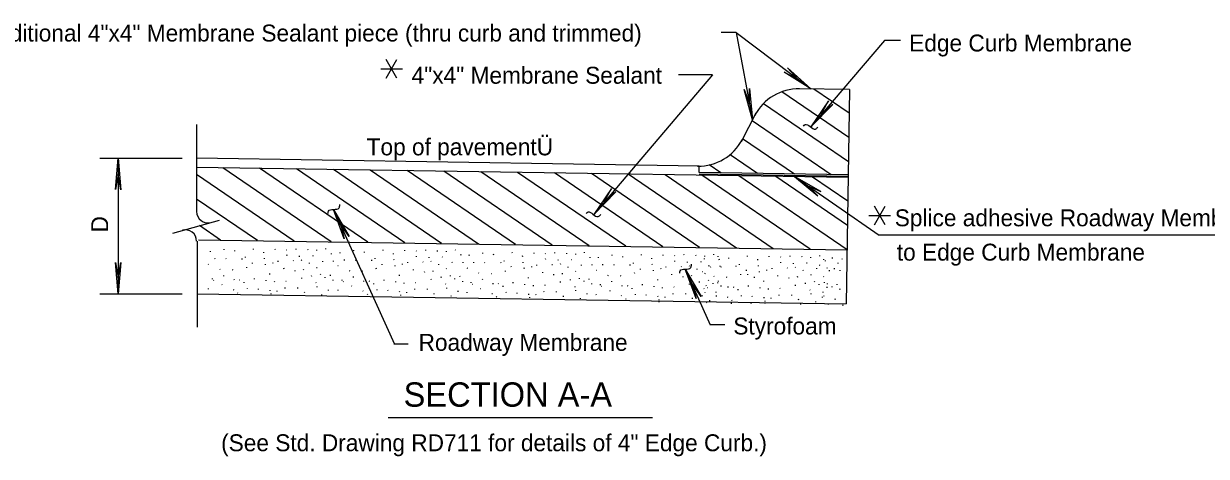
# Model space of a CAD drawing. Extents: x 1000 to 1036, y 1000 to 1022.7.
# Drawn here: x 1012.07 to 1022.98, y 1008.69 to 1012.68 of the extents above; entities that cross this region are included whole.
import ezdxf

# ---------------------------------------------------------------- set-up
doc = ezdxf.new("R2010")
doc.units = 0
for name, color, linetype in [('rd_Detail Annotation_z_n', 7, 'Continuous'), ('rd_Details_z_n', 7, 'Continuous'), ('rd_Dimensions_z_n', 7, 'Continuous'), ('rd_Misc Label_z_n', 7, 'Continuous'), ('rd_Symbols_z_n', 7, 'Continuous')]:
    doc.layers.add(name, color=color, linetype=linetype)

msp = doc.modelspace()

# ---------------------------------------------------------------- linework, layer by layer
at = {"layer": 'rd_Detail Annotation_z_n'}
for p, q in [((1018.644, 1012.601), (1018.506, 1012.601)), ((1018.644, 1012.601), (1018.797, 1011.796)), ((1018.644, 1012.601), (1019.335, 1012.08)), ((1020.013, 1012.528), (1019.334, 1011.729)), ((1020.161, 1012.528), (1020.013, 1012.528)), ((1018.427, 1012.21), (1017.332, 1010.922)), ((1018.427, 1012.21), (1018.112, 1012.21)), ((1019.182, 1011.273), (1019.963, 1010.731)), ((1014.932, 1010.968), (1015.493, 1009.723)), ((1023.768, 1010.731), (1019.963, 1010.731)), ((1018.176, 1010.417), (1018.407, 1009.903)), ((1018.541, 1009.903), (1018.407, 1009.903)), ((1015.621, 1009.723), (1015.487, 1009.723)), ((1015.437, 1009.045), (1017.874, 1009.045))]:
    msp.add_line(p, q, dxfattribs=at)
at = {"layer": 'rd_Details_z_n'}
for p, q in [((1019.691, 1012.074), (1019.226, 1012.081)), ((1019.687, 1011.857), (1019.362, 1012.079)), ((1019.691, 1012.074), (1019.66, 1010.095)), ((1019.684, 1011.633), (1019.067, 1012.054)), ((1018.828, 1011.856), (1018.691, 1011.593)), ((1019.68, 1011.408), (1018.896, 1011.944)), ((1013.669, 1011.752), (1013.669, 1010.947)), ((1019.523, 1011.288), (1018.793, 1011.787)), ((1019.183, 1011.294), (1018.705, 1011.62)), ((1018.305, 1011.366), (1013.669, 1011.44)), ((1018.843, 1011.299), (1018.589, 1011.473)), ((1019.678, 1011.261), (1013.669, 1011.356)), ((1014.909, 1010.669), (1013.91, 1011.352)), ((1015.249, 1010.664), (1014.25, 1011.347)), ((1015.589, 1010.659), (1014.59, 1011.342)), ((1015.929, 1010.653), (1014.93, 1011.336)), ((1016.269, 1010.648), (1015.27, 1011.331)), ((1016.609, 1010.643), (1015.61, 1011.326)), ((1016.949, 1010.637), (1015.95, 1011.32)), ((1017.289, 1010.632), (1016.29, 1011.315)), ((1017.628, 1010.627), (1016.63, 1011.309)), ((1017.968, 1010.621), (1016.97, 1011.304)), ((1018.308, 1010.616), (1017.31, 1011.299)), ((1018.648, 1010.611), (1017.65, 1011.293)), ((1018.304, 1011.308), (1018.305, 1011.366)), ((1019.679, 1011.286), (1018.304, 1011.308)), ((1019.679, 1011.273), (1018.304, 1011.294)), ((1018.503, 1011.304), (1018.396, 1011.378)), ((1014.569, 1010.675), (1013.669, 1011.29)), ((1018.988, 1010.605), (1017.99, 1011.288)), ((1019.328, 1010.6), (1018.33, 1011.283)), ((1019.668, 1010.595), (1018.67, 1011.277)), ((1019.671, 1010.82), (1019.01, 1011.272)), ((1019.675, 1011.044), (1019.35, 1011.266)), ((1014.229, 1010.68), (1013.669, 1011.063)), ((1013.45, 1010.749), (1013.879, 1010.869)), ((1013.889, 1010.685), (1013.695, 1010.818)), ((1013.673, 1010.675), (1013.673, 1009.879)), ((1013.685, 1010.688), (1019.668, 1010.595)), ((1013.798, 1010.575), (1013.798, 1010.582)), ((1013.923, 1010.596), (1013.923, 1010.602)), ((1014.022, 1010.581), (1014.022, 1010.588)), ((1014.121, 1010.523), (1014.121, 1010.529)), ((1014.194, 1010.598), (1014.193, 1010.605)), ((1014.29, 1010.566), (1014.289, 1010.573)), ((1014.395, 1010.596), (1014.394, 1010.602)), ((1014.498, 1010.596), (1014.502, 1010.594)), ((1014.503, 1010.54), (1014.502, 1010.547)), ((1014.587, 1010.598), (1014.586, 1010.605)), ((1014.619, 1010.531), (1014.618, 1010.538)), ((1014.697, 1010.592), (1014.696, 1010.599)), ((1014.738, 1010.541), (1014.743, 1010.539)), ((1014.779, 1010.587), (1014.778, 1010.593)), ((1014.861, 1010.601), (1014.86, 1010.608)), ((1014.913, 1010.555), (1014.912, 1010.561)), ((1014.993, 1010.563), (1014.993, 1010.57)), ((1015.119, 1010.584), (1015.118, 1010.591)), ((1015.218, 1010.569), (1015.217, 1010.576)), ((1015.389, 1010.587), (1015.389, 1010.593)), ((1015.485, 1010.555), (1015.485, 1010.561)), ((1015.59, 1010.584), (1015.589, 1010.591)), ((1015.693, 1010.585), (1015.697, 1010.582)), ((1015.698, 1010.529), (1015.697, 1010.535)), ((1015.782, 1010.587), (1015.782, 1010.593)), ((1015.892, 1010.58), (1015.891, 1010.587)), ((1015.933, 1010.529), (1015.938, 1010.527)), ((1015.974, 1010.575), (1015.974, 1010.582)), ((1016.056, 1010.59), (1016.055, 1010.596)), ((1016.108, 1010.543), (1016.107, 1010.55)), ((1016.185, 1010.54), (1016.184, 1010.547)), ((1016.31, 1010.561), (1016.309, 1010.567)), ((1016.409, 1010.546), (1016.408, 1010.553)), ((1016.581, 1010.563), (1016.58, 1010.57)), ((1016.677, 1010.531), (1016.676, 1010.538)), ((1016.781, 1010.561), (1016.781, 1010.567)), ((1016.884, 1010.561), (1016.888, 1010.559)), ((1016.973, 1010.563), (1016.973, 1010.57)), ((1017.084, 1010.557), (1017.083, 1010.564)), ((1017.166, 1010.552), (1017.165, 1010.559)), ((1017.247, 1010.566), (1017.246, 1010.573)), ((1017.501, 1010.541), (1017.501, 1010.548)), ((1017.6, 1010.527), (1017.6, 1010.533)), ((1017.772, 1010.544), (1017.771, 1010.551)), ((1017.973, 1010.541), (1017.972, 1010.548)), ((1018.076, 1010.542), (1018.08, 1010.54)), ((1018.165, 1010.544), (1018.164, 1010.551)), ((1018.275, 1010.538), (1018.274, 1010.544)), ((1018.357, 1010.532), (1018.356, 1010.539)), ((1018.438, 1010.547), (1018.438, 1010.554)), ((1018.479, 1010.53), (1018.479, 1010.536)), ((1018.75, 1010.532), (1018.749, 1010.539)), ((1018.951, 1010.53), (1018.95, 1010.536)), ((1019.053, 1010.53), (1019.058, 1010.528)), ((1019.143, 1010.532), (1019.142, 1010.539)), ((1019.253, 1010.526), (1019.252, 1010.533)), ((1019.416, 1010.535), (1019.416, 1010.542)), ((1013.776, 1010.462), (1013.78, 1010.46)), ((1013.839, 1010.508), (1013.838, 1010.515)), ((1013.937, 1010.513), (1013.941, 1010.511)), ((1014.09, 1010.506), (1014.089, 1010.513)), ((1014.132, 1010.429), (1014.131, 1010.436)), ((1014.185, 1010.468), (1014.185, 1010.475)), ((1014.295, 1010.51), (1014.294, 1010.517)), ((1014.305, 1010.455), (1014.304, 1010.462)), ((1014.374, 1010.469), (1014.373, 1010.476)), ((1014.421, 1010.485), (1014.42, 1010.492)), ((1014.475, 1010.417), (1014.474, 1010.424)), ((1014.559, 1010.495), (1014.564, 1010.492)), ((1014.634, 1010.502), (1014.638, 1010.497)), ((1014.709, 1010.467), (1014.709, 1010.474)), ((1014.776, 1010.432), (1014.78, 1010.43)), ((1014.833, 1010.484), (1014.832, 1010.491)), ((1014.931, 1010.487), (1014.931, 1010.493)), ((1014.971, 1010.451), (1014.975, 1010.449)), ((1015.034, 1010.497), (1015.034, 1010.504)), ((1015.132, 1010.502), (1015.136, 1010.499)), ((1015.285, 1010.494), (1015.285, 1010.501)), ((1015.316, 1010.511), (1015.316, 1010.518)), ((1015.327, 1010.417), (1015.326, 1010.424)), ((1015.381, 1010.456), (1015.38, 1010.463)), ((1015.49, 1010.499), (1015.489, 1010.505)), ((1015.5, 1010.443), (1015.5, 1010.45)), ((1015.569, 1010.458), (1015.568, 1010.464)), ((1015.616, 1010.474), (1015.616, 1010.48)), ((1015.754, 1010.483), (1015.759, 1010.481)), ((1015.814, 1010.52), (1015.814, 1010.526)), ((1015.83, 1010.491), (1015.833, 1010.486)), ((1015.904, 1010.456), (1015.904, 1010.462)), ((1015.971, 1010.421), (1015.975, 1010.418)), ((1016.028, 1010.473), (1016.027, 1010.48)), ((1016.126, 1010.475), (1016.126, 1010.482)), ((1016.162, 1010.428), (1016.167, 1010.425)), ((1016.226, 1010.474), (1016.225, 1010.48)), ((1016.323, 1010.478), (1016.328, 1010.476)), ((1016.477, 1010.471), (1016.476, 1010.478)), ((1016.508, 1010.488), (1016.507, 1010.494)), ((1016.572, 1010.433), (1016.571, 1010.44)), ((1016.681, 1010.475), (1016.68, 1010.482)), ((1016.692, 1010.42), (1016.691, 1010.427)), ((1016.76, 1010.434), (1016.76, 1010.441)), ((1016.808, 1010.45), (1016.807, 1010.457)), ((1016.889, 1010.505), (1016.888, 1010.512)), ((1016.946, 1010.46), (1016.95, 1010.458)), ((1017.006, 1010.497), (1017.005, 1010.503)), ((1017.021, 1010.467), (1017.025, 1010.462)), ((1017.096, 1010.432), (1017.095, 1010.439)), ((1017.125, 1010.506), (1017.129, 1010.504)), ((1017.22, 1010.45), (1017.219, 1010.456)), ((1017.299, 1010.52), (1017.299, 1010.526)), ((1017.318, 1010.452), (1017.317, 1010.458)), ((1017.376, 1010.521), (1017.375, 1010.527)), ((1017.417, 1010.454), (1017.416, 1010.461)), ((1017.514, 1010.459), (1017.519, 1010.457)), ((1017.668, 1010.451), (1017.667, 1010.458)), ((1017.699, 1010.468), (1017.699, 1010.475)), ((1017.763, 1010.413), (1017.763, 1010.42)), ((1017.868, 1010.512), (1017.867, 1010.519)), ((1017.873, 1010.456), (1017.872, 1010.463)), ((1017.952, 1010.415), (1017.951, 1010.422)), ((1017.999, 1010.431), (1017.998, 1010.438)), ((1018.08, 1010.486), (1018.08, 1010.493)), ((1018.137, 1010.441), (1018.142, 1010.438)), ((1018.197, 1010.477), (1018.196, 1010.484)), ((1018.212, 1010.448), (1018.216, 1010.443)), ((1018.287, 1010.413), (1018.286, 1010.42)), ((1018.316, 1010.487), (1018.321, 1010.484)), ((1018.354, 1010.509), (1018.353, 1010.516)), ((1018.395, 1010.442), (1018.394, 1010.449)), ((1018.411, 1010.43), (1018.41, 1010.437)), ((1018.491, 1010.5), (1018.49, 1010.507)), ((1018.492, 1010.447), (1018.497, 1010.445)), ((1018.509, 1010.432), (1018.508, 1010.439)), ((1018.578, 1010.515), (1018.577, 1010.522)), ((1018.646, 1010.44), (1018.645, 1010.447)), ((1018.677, 1010.457), (1018.676, 1010.463)), ((1018.846, 1010.5), (1018.845, 1010.507)), ((1018.85, 1010.444), (1018.85, 1010.451)), ((1018.977, 1010.419), (1018.976, 1010.426)), ((1019.058, 1010.474), (1019.058, 1010.481)), ((1019.115, 1010.429), (1019.12, 1010.426)), ((1019.175, 1010.465), (1019.174, 1010.472)), ((1019.19, 1010.436), (1019.194, 1010.431)), ((1019.294, 1010.475), (1019.299, 1010.473)), ((1019.335, 1010.521), (1019.334, 1010.527)), ((1019.389, 1010.418), (1019.388, 1010.425)), ((1019.412, 1010.456), (1019.417, 1010.453)), ((1019.453, 1010.501), (1019.453, 1010.508)), ((1019.469, 1010.489), (1019.468, 1010.495)), ((1019.487, 1010.421), (1019.486, 1010.427)), ((1019.535, 1010.516), (1019.534, 1010.523)), ((1019.553, 1010.417), (1019.552, 1010.424)), ((1019.587, 1010.469), (1019.586, 1010.476)), ((1019.625, 1010.504), (1019.624, 1010.511)), ((1013.815, 1010.324), (1013.815, 1010.33)), ((1013.824, 1010.314), (1013.827, 1010.312)), ((1013.882, 1010.416), (1013.886, 1010.414)), ((1013.921, 1010.352), (1013.921, 1010.359)), ((1013.998, 1010.412), (1014.003, 1010.409)), ((1014.017, 1010.314), (1014.016, 1010.321)), ((1014.063, 1010.318), (1014.067, 1010.316)), ((1014.204, 1010.323), (1014.203, 1010.33)), ((1014.311, 1010.307), (1014.31, 1010.314)), ((1014.345, 1010.368), (1014.344, 1010.375)), ((1014.577, 1010.397), (1014.577, 1010.403)), ((1014.638, 1010.329), (1014.638, 1010.336)), ((1014.657, 1010.406), (1014.656, 1010.413)), ((1014.731, 1010.348), (1014.73, 1010.355)), ((1014.814, 1010.363), (1014.813, 1010.369)), ((1014.856, 1010.336), (1014.856, 1010.343)), ((1014.904, 1010.356), (1014.903, 1010.363)), ((1014.929, 1010.311), (1014.928, 1010.318)), ((1015.011, 1010.312), (1015.01, 1010.319)), ((1015.077, 1010.404), (1015.082, 1010.402)), ((1015.117, 1010.34), (1015.116, 1010.347)), ((1015.194, 1010.4), (1015.198, 1010.398)), ((1015.399, 1010.312), (1015.398, 1010.319)), ((1015.54, 1010.356), (1015.539, 1010.363)), ((1015.67, 1010.406), (1015.67, 1010.413)), ((1015.773, 1010.385), (1015.772, 1010.392)), ((1015.834, 1010.317), (1015.833, 1010.324)), ((1015.852, 1010.395), (1015.851, 1010.401)), ((1015.926, 1010.337), (1015.925, 1010.344)), ((1016.009, 1010.351), (1016.009, 1010.358)), ((1016.052, 1010.324), (1016.051, 1010.331)), ((1016.099, 1010.344), (1016.098, 1010.351)), ((1016.268, 1010.381), (1016.273, 1010.379)), ((1016.308, 1010.317), (1016.307, 1010.324)), ((1016.385, 1010.377), (1016.389, 1010.375)), ((1016.518, 1010.394), (1016.517, 1010.401)), ((1016.731, 1010.333), (1016.73, 1010.34)), ((1016.862, 1010.383), (1016.861, 1010.389)), ((1016.964, 1010.362), (1016.963, 1010.369)), ((1017.043, 1010.371), (1017.043, 1010.378)), ((1017.117, 1010.313), (1017.116, 1010.321)), ((1017.162, 1010.397), (1017.167, 1010.395)), ((1017.201, 1010.328), (1017.2, 1010.334)), ((1017.29, 1010.321), (1017.289, 1010.328)), ((1017.353, 1010.408), (1017.358, 1010.406)), ((1017.46, 1010.362), (1017.464, 1010.359)), ((1017.576, 1010.358), (1017.581, 1010.355)), ((1017.71, 1010.375), (1017.709, 1010.382)), ((1017.883, 1010.401), (1017.882, 1010.407)), ((1017.923, 1010.313), (1017.922, 1010.32)), ((1018.053, 1010.363), (1018.052, 1010.37)), ((1018.155, 1010.342), (1018.155, 1010.349)), ((1018.235, 1010.352), (1018.234, 1010.359)), ((1018.331, 1010.396), (1018.336, 1010.394)), ((1018.354, 1010.378), (1018.358, 1010.376)), ((1018.392, 1010.308), (1018.391, 1010.315)), ((1018.438, 1010.35), (1018.442, 1010.348)), ((1018.554, 1010.346), (1018.559, 1010.343)), ((1018.687, 1010.363), (1018.687, 1010.37)), ((1018.741, 1010.402), (1018.74, 1010.409)), ((1018.754, 1010.365), (1018.753, 1010.371)), ((1018.814, 1010.337), (1018.813, 1010.344)), ((1018.861, 1010.389), (1018.86, 1010.396)), ((1018.929, 1010.403), (1018.929, 1010.41)), ((1019.031, 1010.351), (1019.03, 1010.358)), ((1019.133, 1010.331), (1019.132, 1010.337)), ((1019.213, 1010.34), (1019.212, 1010.347)), ((1019.265, 1010.401), (1019.264, 1010.408)), ((1019.331, 1010.366), (1019.336, 1010.364)), ((1019.45, 1010.347), (1019.454, 1010.345)), ((1019.507, 1010.399), (1019.506, 1010.406)), ((1019.605, 1010.401), (1019.605, 1010.408)), ((1013.778, 1010.231), (1013.777, 1010.238)), ((1013.901, 1010.274), (1013.905, 1010.271)), ((1014.007, 1010.227), (1014.011, 1010.225)), ((1014.109, 1010.289), (1014.108, 1010.296)), ((1014.139, 1010.233), (1014.138, 1010.239)), ((1014.239, 1010.227), (1014.239, 1010.234)), ((1014.347, 1010.215), (1014.346, 1010.222)), ((1014.389, 1010.295), (1014.388, 1010.302)), ((1014.413, 1010.21), (1014.412, 1010.216)), ((1014.487, 1010.239), (1014.486, 1010.246)), ((1014.492, 1010.306), (1014.496, 1010.304)), ((1014.603, 1010.239), (1014.602, 1010.246)), ((1014.666, 1010.197), (1014.665, 1010.204)), ((1014.768, 1010.292), (1014.773, 1010.289)), ((1014.782, 1010.25), (1014.781, 1010.257)), ((1014.885, 1010.219), (1014.885, 1010.226)), ((1014.973, 1010.219), (1014.973, 1010.226)), ((1015.02, 1010.302), (1015.023, 1010.3)), ((1015.096, 1010.262), (1015.1, 1010.259)), ((1015.202, 1010.215), (1015.206, 1010.213)), ((1015.212, 1010.302), (1015.211, 1010.309)), ((1015.258, 1010.307), (1015.262, 1010.304)), ((1015.304, 1010.277), (1015.303, 1010.284)), ((1015.334, 1010.221), (1015.333, 1010.228)), ((1015.435, 1010.215), (1015.434, 1010.222)), ((1015.506, 1010.295), (1015.505, 1010.302)), ((1015.542, 1010.203), (1015.541, 1010.21)), ((1015.584, 1010.284), (1015.584, 1010.29)), ((1015.608, 1010.198), (1015.608, 1010.205)), ((1015.682, 1010.228), (1015.681, 1010.235)), ((1015.687, 1010.294), (1015.691, 1010.292)), ((1015.798, 1010.228), (1015.797, 1010.235)), ((1015.964, 1010.28), (1015.968, 1010.278)), ((1015.977, 1010.238), (1015.976, 1010.245)), ((1016.081, 1010.208), (1016.08, 1010.215)), ((1016.124, 1010.3), (1016.123, 1010.306)), ((1016.165, 1010.196), (1016.164, 1010.203)), ((1016.202, 1010.289), (1016.201, 1010.295)), ((1016.211, 1010.279), (1016.214, 1010.277)), ((1016.287, 1010.239), (1016.291, 1010.236)), ((1016.403, 1010.279), (1016.403, 1010.286)), ((1016.449, 1010.283), (1016.454, 1010.281)), ((1016.495, 1010.254), (1016.495, 1010.261)), ((1016.526, 1010.198), (1016.525, 1010.204)), ((1016.59, 1010.288), (1016.589, 1010.295)), ((1016.697, 1010.272), (1016.696, 1010.279)), ((1016.776, 1010.26), (1016.775, 1010.267)), ((1016.873, 1010.204), (1016.872, 1010.211)), ((1016.878, 1010.271), (1016.883, 1010.269)), ((1016.989, 1010.204), (1016.988, 1010.211)), ((1017.025, 1010.294), (1017.024, 1010.301)), ((1017.155, 1010.257), (1017.16, 1010.254)), ((1017.168, 1010.215), (1017.167, 1010.222)), ((1017.243, 1010.301), (1017.242, 1010.308)), ((1017.315, 1010.276), (1017.315, 1010.283)), ((1017.393, 1010.269), (1017.393, 1010.276)), ((1017.402, 1010.259), (1017.405, 1010.258)), ((1017.478, 1010.219), (1017.483, 1010.217)), ((1017.499, 1010.298), (1017.499, 1010.304)), ((1017.595, 1010.259), (1017.594, 1010.266)), ((1017.641, 1010.264), (1017.645, 1010.261)), ((1017.687, 1010.234), (1017.686, 1010.241)), ((1017.781, 1010.269), (1017.781, 1010.276)), ((1017.889, 1010.252), (1017.888, 1010.259)), ((1017.967, 1010.241), (1017.966, 1010.248)), ((1018.069, 1010.252), (1018.074, 1010.249)), ((1018.216, 1010.275), (1018.216, 1010.282)), ((1018.308, 1010.294), (1018.308, 1010.301)), ((1018.346, 1010.237), (1018.351, 1010.235)), ((1018.36, 1010.196), (1018.359, 1010.202)), ((1018.371, 1010.258), (1018.37, 1010.264)), ((1018.38, 1010.248), (1018.383, 1010.246)), ((1018.434, 1010.282), (1018.433, 1010.288)), ((1018.456, 1010.208), (1018.461, 1010.205)), ((1018.477, 1010.286), (1018.477, 1010.293)), ((1018.482, 1010.302), (1018.481, 1010.308)), ((1018.507, 1010.257), (1018.506, 1010.264)), ((1018.573, 1010.248), (1018.572, 1010.255)), ((1018.618, 1010.252), (1018.623, 1010.25)), ((1018.665, 1010.223), (1018.664, 1010.23)), ((1018.759, 1010.257), (1018.759, 1010.264)), ((1018.866, 1010.241), (1018.866, 1010.248)), ((1018.9, 1010.302), (1018.9, 1010.309)), ((1018.945, 1010.229), (1018.944, 1010.236)), ((1019.047, 1010.24), (1019.052, 1010.238)), ((1019.194, 1010.263), (1019.193, 1010.27)), ((1019.286, 1010.282), (1019.286, 1010.289)), ((1019.324, 1010.226), (1019.329, 1010.223)), ((1019.37, 1010.297), (1019.369, 1010.303)), ((1019.412, 1010.27), (1019.411, 1010.277)), ((1019.443, 1010.206), (1019.447, 1010.204)), ((1019.459, 1010.29), (1019.459, 1010.297)), ((1019.485, 1010.245), (1019.484, 1010.252)), ((1019.488, 1010.277), (1019.487, 1010.284)), ((1019.531, 1010.251), (1019.53, 1010.257)), ((1019.578, 1010.271), (1019.577, 1010.277)), ((1019.603, 1010.226), (1019.602, 1010.233)), ((1013.673, 1010.189), (1019.66, 1010.095)), ((1014.046, 1010.199), (1014.05, 1010.194)), ((1014.356, 1010.185), (1014.356, 1010.191)), ((1014.824, 1010.176), (1014.823, 1010.183)), ((1015.241, 1010.188), (1015.245, 1010.182)), ((1015.552, 1010.173), (1015.551, 1010.18)), ((1015.861, 1010.186), (1015.86, 1010.192)), ((1016.019, 1010.164), (1016.018, 1010.171)), ((1016.393, 1010.192), (1016.398, 1010.19)), ((1016.433, 1010.164), (1016.437, 1010.159)), ((1016.626, 1010.192), (1016.625, 1010.199)), ((1016.734, 1010.18), (1016.733, 1010.187)), ((1016.743, 1010.15), (1016.742, 1010.157)), ((1016.8, 1010.175), (1016.799, 1010.182)), ((1017.052, 1010.162), (1017.052, 1010.169)), ((1017.21, 1010.141), (1017.21, 1010.148)), ((1017.272, 1010.185), (1017.271, 1010.191)), ((1017.356, 1010.176), (1017.355, 1010.183)), ((1017.584, 1010.172), (1017.589, 1010.17)), ((1017.624, 1010.145), (1017.628, 1010.14)), ((1017.717, 1010.178), (1017.716, 1010.185)), ((1017.817, 1010.172), (1017.816, 1010.179)), ((1017.925, 1010.161), (1017.924, 1010.167)), ((1017.934, 1010.13), (1017.934, 1010.137)), ((1017.936, 1010.111), (1017.935, 1010.117)), ((1017.991, 1010.155), (1017.99, 1010.162)), ((1018.064, 1010.185), (1018.064, 1010.192)), ((1018.18, 1010.185), (1018.18, 1010.192)), ((1018.244, 1010.143), (1018.243, 1010.15)), ((1018.334, 1010.165), (1018.333, 1010.172)), ((1018.372, 1010.108), (1018.376, 1010.106)), ((1018.402, 1010.122), (1018.401, 1010.129)), ((1018.463, 1010.165), (1018.463, 1010.172)), ((1018.562, 1010.161), (1018.567, 1010.159)), ((1018.602, 1010.097), (1018.601, 1010.104)), ((1018.602, 1010.133), (1018.606, 1010.128)), ((1018.695, 1010.167), (1018.694, 1010.173)), ((1018.786, 1010.096), (1018.785, 1010.103)), ((1018.795, 1010.161), (1018.794, 1010.167)), ((1018.903, 1010.149), (1018.902, 1010.156)), ((1018.912, 1010.119), (1018.912, 1010.125)), ((1018.914, 1010.099), (1018.913, 1010.106)), ((1018.969, 1010.144), (1018.968, 1010.15)), ((1019.042, 1010.173), (1019.042, 1010.18)), ((1019.158, 1010.173), (1019.158, 1010.18)), ((1019.222, 1010.131), (1019.221, 1010.138)), ((1019.243, 1010.089), (1019.242, 1010.096)), ((1019.337, 1010.184), (1019.337, 1010.191)), ((1019.38, 1010.11), (1019.379, 1010.117)), ((1019.441, 1010.153), (1019.44, 1010.16)), ((1019.456, 1010.164), (1019.455, 1010.171)), ((1019.498, 1010.091), (1019.497, 1010.097)), ((1019.56, 1010.134), (1019.559, 1010.141)), ((1019.631, 1010.079), (1019.63, 1010.086))]:
    msp.add_line(p, q, dxfattribs=at)
for centre, radius, start, end in [((1019.223, 1011.624), 0.457, 89.1001, 152.4699), ((1018.296, 1011.824), 0.457, 269.0822, 332.4766), ((1013.773, 1010.947), 0.104, 180, 285.1902), ((1013.565, 1010.675), 0.104, 0, 105.1902)]:
    msp.add_arc(centre, radius, start, end, dxfattribs=at)
for points in [[(1019.265, 1011.737), (1019.282, 1011.752), (1019.327, 1011.733), (1019.376, 1011.709), (1019.399, 1011.728)], [(1014.881, 1010.93), (1014.885, 1010.953), (1014.93, 1010.968), (1014.983, 1010.982), (1014.989, 1011.012)], [(1017.262, 1010.93), (1017.28, 1010.944), (1017.324, 1010.925), (1017.373, 1010.902), (1017.397, 1010.92)], [(1018.125, 1010.379), (1018.129, 1010.401), (1018.175, 1010.416), (1018.227, 1010.431), (1018.233, 1010.461)]]:
    msp.add_spline(points, degree=3, dxfattribs=at)
at = {"layer": 'rd_Dimensions_z_n'}
for p, q in [((1012.777, 1011.44), (1013.535, 1011.44)), ((1012.946, 1011.44), (1012.946, 1010.189)), ((1012.777, 1010.189), (1013.535, 1010.189))]:
    msp.add_line(p, q, dxfattribs=at)
at = {"layer": 'rd_Misc Label_z_n'}
for points in [[(1019.12, 1012.274), (1019.335, 1012.08), (1019.089, 1012.234), (1019.215, 1012.17), (1019.12, 1012.274)], [(1018.769, 1012.085), (1018.797, 1011.796), (1018.719, 1012.075), (1018.769, 1011.943), (1018.769, 1012.085)], [(1019.498, 1011.969), (1019.334, 1011.729), (1019.537, 1011.937), (1019.429, 1011.846), (1019.498, 1011.969)], [(1012.921, 1011.151), (1012.946, 1011.44), (1012.971, 1011.15), (1012.946, 1011.29), (1012.921, 1011.151)], [(1019.425, 1011.134), (1019.182, 1011.273), (1019.398, 1011.094), (1019.301, 1011.19), (1019.425, 1011.134)], [(1017.495, 1011.162), (1017.332, 1010.922), (1017.534, 1011.13), (1017.427, 1011.038), (1017.495, 1011.162)], [(1015.031, 1010.695), (1014.932, 1010.968), (1015.077, 1010.717), (1014.995, 1010.832), (1015.031, 1010.695)], [(1012.971, 1010.478), (1012.946, 1010.189), (1012.921, 1010.478), (1012.946, 1010.339), (1012.971, 1010.478)], [(1018.275, 1010.144), (1018.176, 1010.417), (1018.321, 1010.165), (1018.239, 1010.281), (1018.275, 1010.144)]]:
    msp.add_lwpolyline(points, dxfattribs=at)
at = {"layer": 'rd_Symbols_z_n'}
for p, q in [((1015.417, 1012.179), (1015.517, 1012.352)), ((1015.517, 1012.179), (1015.417, 1012.352)), ((1015.367, 1012.265), (1015.567, 1012.265)), ((1019.92, 1010.825), (1020.02, 1010.998)), ((1020.02, 1010.825), (1019.92, 1010.998)), ((1019.87, 1010.912), (1020.07, 1010.912))]:
    msp.add_line(p, q, dxfattribs=at)

# ---------------------------------------------------------------- texts
at = {"layer": 'rd_Detail Annotation_z_n'}
for s, height, p in [('Additional 4"x4" Membrane Sealant piece (thru curb and trimmed) ', 0.15628, (1011.69, 1012.518)), ('Edge Curb Membrane', 0.15628, (1020.241, 1012.426)), ('4"x4" Membrane Sealant', 0.15628, (1015.652, 1012.128)), ('Top of pavementÜ', 0.15628, (1015.237, 1011.467)), ('Splice adhesive Roadway Membrane', 0.15628, (1020.108, 1010.812)), ('to Edge Curb Membrane', 0.15628, (1020.127, 1010.495)), ('Styrofoam', 0.1563, (1018.619, 1009.813)), ('Roadway Membrane', 0.15628, (1015.716, 1009.662)), ('SECTION A-A', 0.225, (1015.578, 1009.146)), ('(See Std. Drawing RD711 for details of 4" Edge Curb.)', 0.15628, (1013.895, 1008.735))]:
    msp.add_text(s, height=height, dxfattribs=at).set_placement(p)
at = {"layer": 'rd_Dimensions_z_n'}
msp.add_text('D', height=0.156, rotation=90, dxfattribs=at).set_placement((1012.853, 1010.755))

doc.saveas('drawing.dxf')
